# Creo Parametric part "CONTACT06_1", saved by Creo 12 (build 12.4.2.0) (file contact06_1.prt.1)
Units: Custom; MM, KILOGRAM, SECS

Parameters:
  PTC_WM_ITERATION = "0"
  PTC_WM_VERSION = "-.0"
  PTC_WM_LIFECYCLE_STATE = "In Work"
  PTC_WM_LIFECYCLE = "MO_CADDocument"
  PTC_WM_CREATED_BY = "Maximilian Roepper (Z0017RMS: MO)"
  PTC_WM_CREATED_ON = "18-Sep-26 11:36:42 AM"
  PTC_WM_MODIFIED_BY = "Maximilian Roepper (Z0017RMS: MO)"
  PTC_WM_MODIFIED_ON = "18-Sep-26 11:36:46 AM"
  PDMLINKNUMBER = "PDM000071454872"
  PTC_WM_NAME = "contact06_1.prt"
  PTC_WM_NUMBER = "PDM000071454872"

Other parameters: WEIGHT, WEIGHT_FACTOR, WEIGHT_ADD, _MASS_TEMP, _DIFF_TEMP, MC_ERRORS, SUPPLIER

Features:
  1. coordinate system
  2. datum plane "PRT_YZ"
  3. datum plane "PRT_XY"
  4. datum plane "PRT_XZ"
  5. coordinate system
  6. datum axis
  7. datum axis
  8. datum axis
  9. coordinate system
  10. imported feature

Other named items: PRT, SIEMENS_MO, DRW_VIEW_ORG, PRT_X, PRT_Y, PRT_Z, CS0, ROUGH_GROB

Layers: 00_STD_CSYS-KSYS, 01_STD_PLANES-EBENEN, 02_STD_AXES-ACHSEN, 03_STD_CSYS-KSYS, 24_IMPORT_FEAT-IMPORT_KE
